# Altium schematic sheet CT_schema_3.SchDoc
size 283 x 147 mm
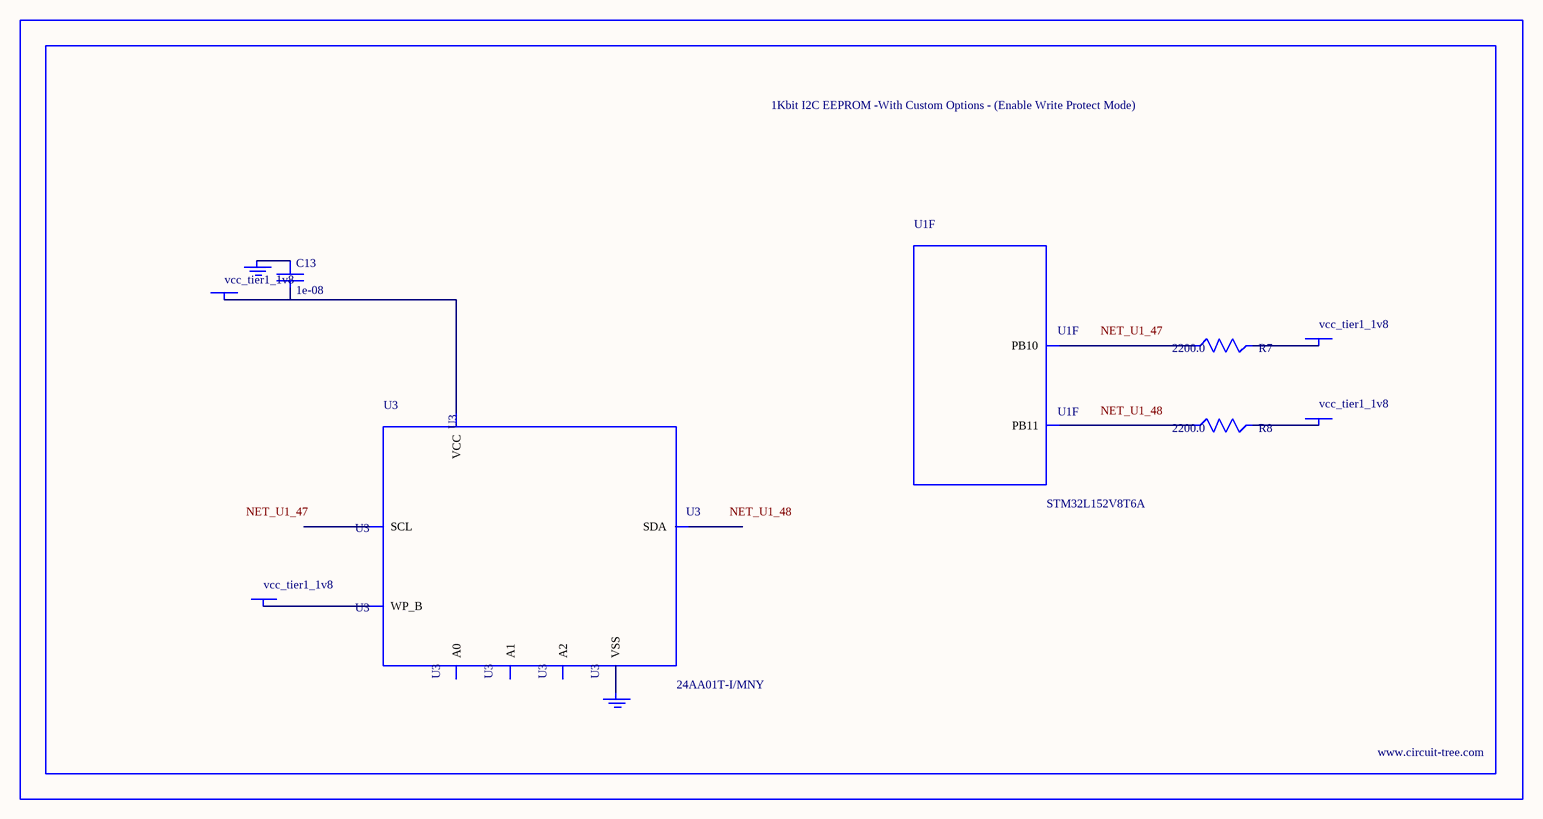
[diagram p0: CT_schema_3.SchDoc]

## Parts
BORDER2  (no value)
C13  1e-08  [C0402]
GND_INSTANCE_2_0  (no value)
GND_INSTANCE_2_1  (no value)
POWER_INSTANCE_2_0  vcc_tier1_1v8
POWER_INSTANCE_2_1  vcc_tier1_1v8
POWER_INSTANCE_2_2  vcc_tier1_1v8
POWER_INSTANCE_2_3  vcc_tier1_1v8
R7  2200.0  [R0603]
R8  2200.0  [R0603]
U1  STM32L152V8T6A  [LQFP100]  (part F of 9)
U3  24AA01T-I/MNY  [TDFN-8/6MM]

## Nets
NetC13_1: C13.1 GND_INSTANCE_2_0.0(GND)
NetC13_2: C13.2 POWER_INSTANCE_2_1.0(PWR) U3.8(VCC)
NetGND_INSTANCE_2_1_0: GND_INSTANCE_2_1.0(GND) U3.4(VSS)
NetPOWER_INSTANCE_2_0_0: POWER_INSTANCE_2_0.0(PWR) U3.7(WP_B)
NetPOWER_INSTANCE_2_2_0: POWER_INSTANCE_2_2.0(PWR) R7.2
NetPOWER_INSTANCE_2_3_0: POWER_INSTANCE_2_3.0(PWR) R8.2
NetR7_1: R7.1 U1.47(PB10)
NetR8_1: R8.1 U1.48(PB11)

Not connected (* = marked no-connect by the designer): U3 1(A0) 2(A1) 3(A2) 5(SDA) 6(SCL)

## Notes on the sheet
- Labels drawn without touching a wire or pin: NET_U1_47, NET_U1_48

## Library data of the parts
BORDER2 = BORDER_PAGE2
C13 = C0402C103K3RAC
GND_INSTANCE_2_0 GND_INSTANCE_2_1 = GND
POWER_INSTANCE_2_0-POWER_INSTANCE_2_3 = PWR
R7 R8 = RC0603JR-072K2L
